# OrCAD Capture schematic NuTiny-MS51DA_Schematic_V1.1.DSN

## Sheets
1 Nu-Link-ME V3.0: size A4; title: Nu-Link-Me; rev: 3.0; note: 1
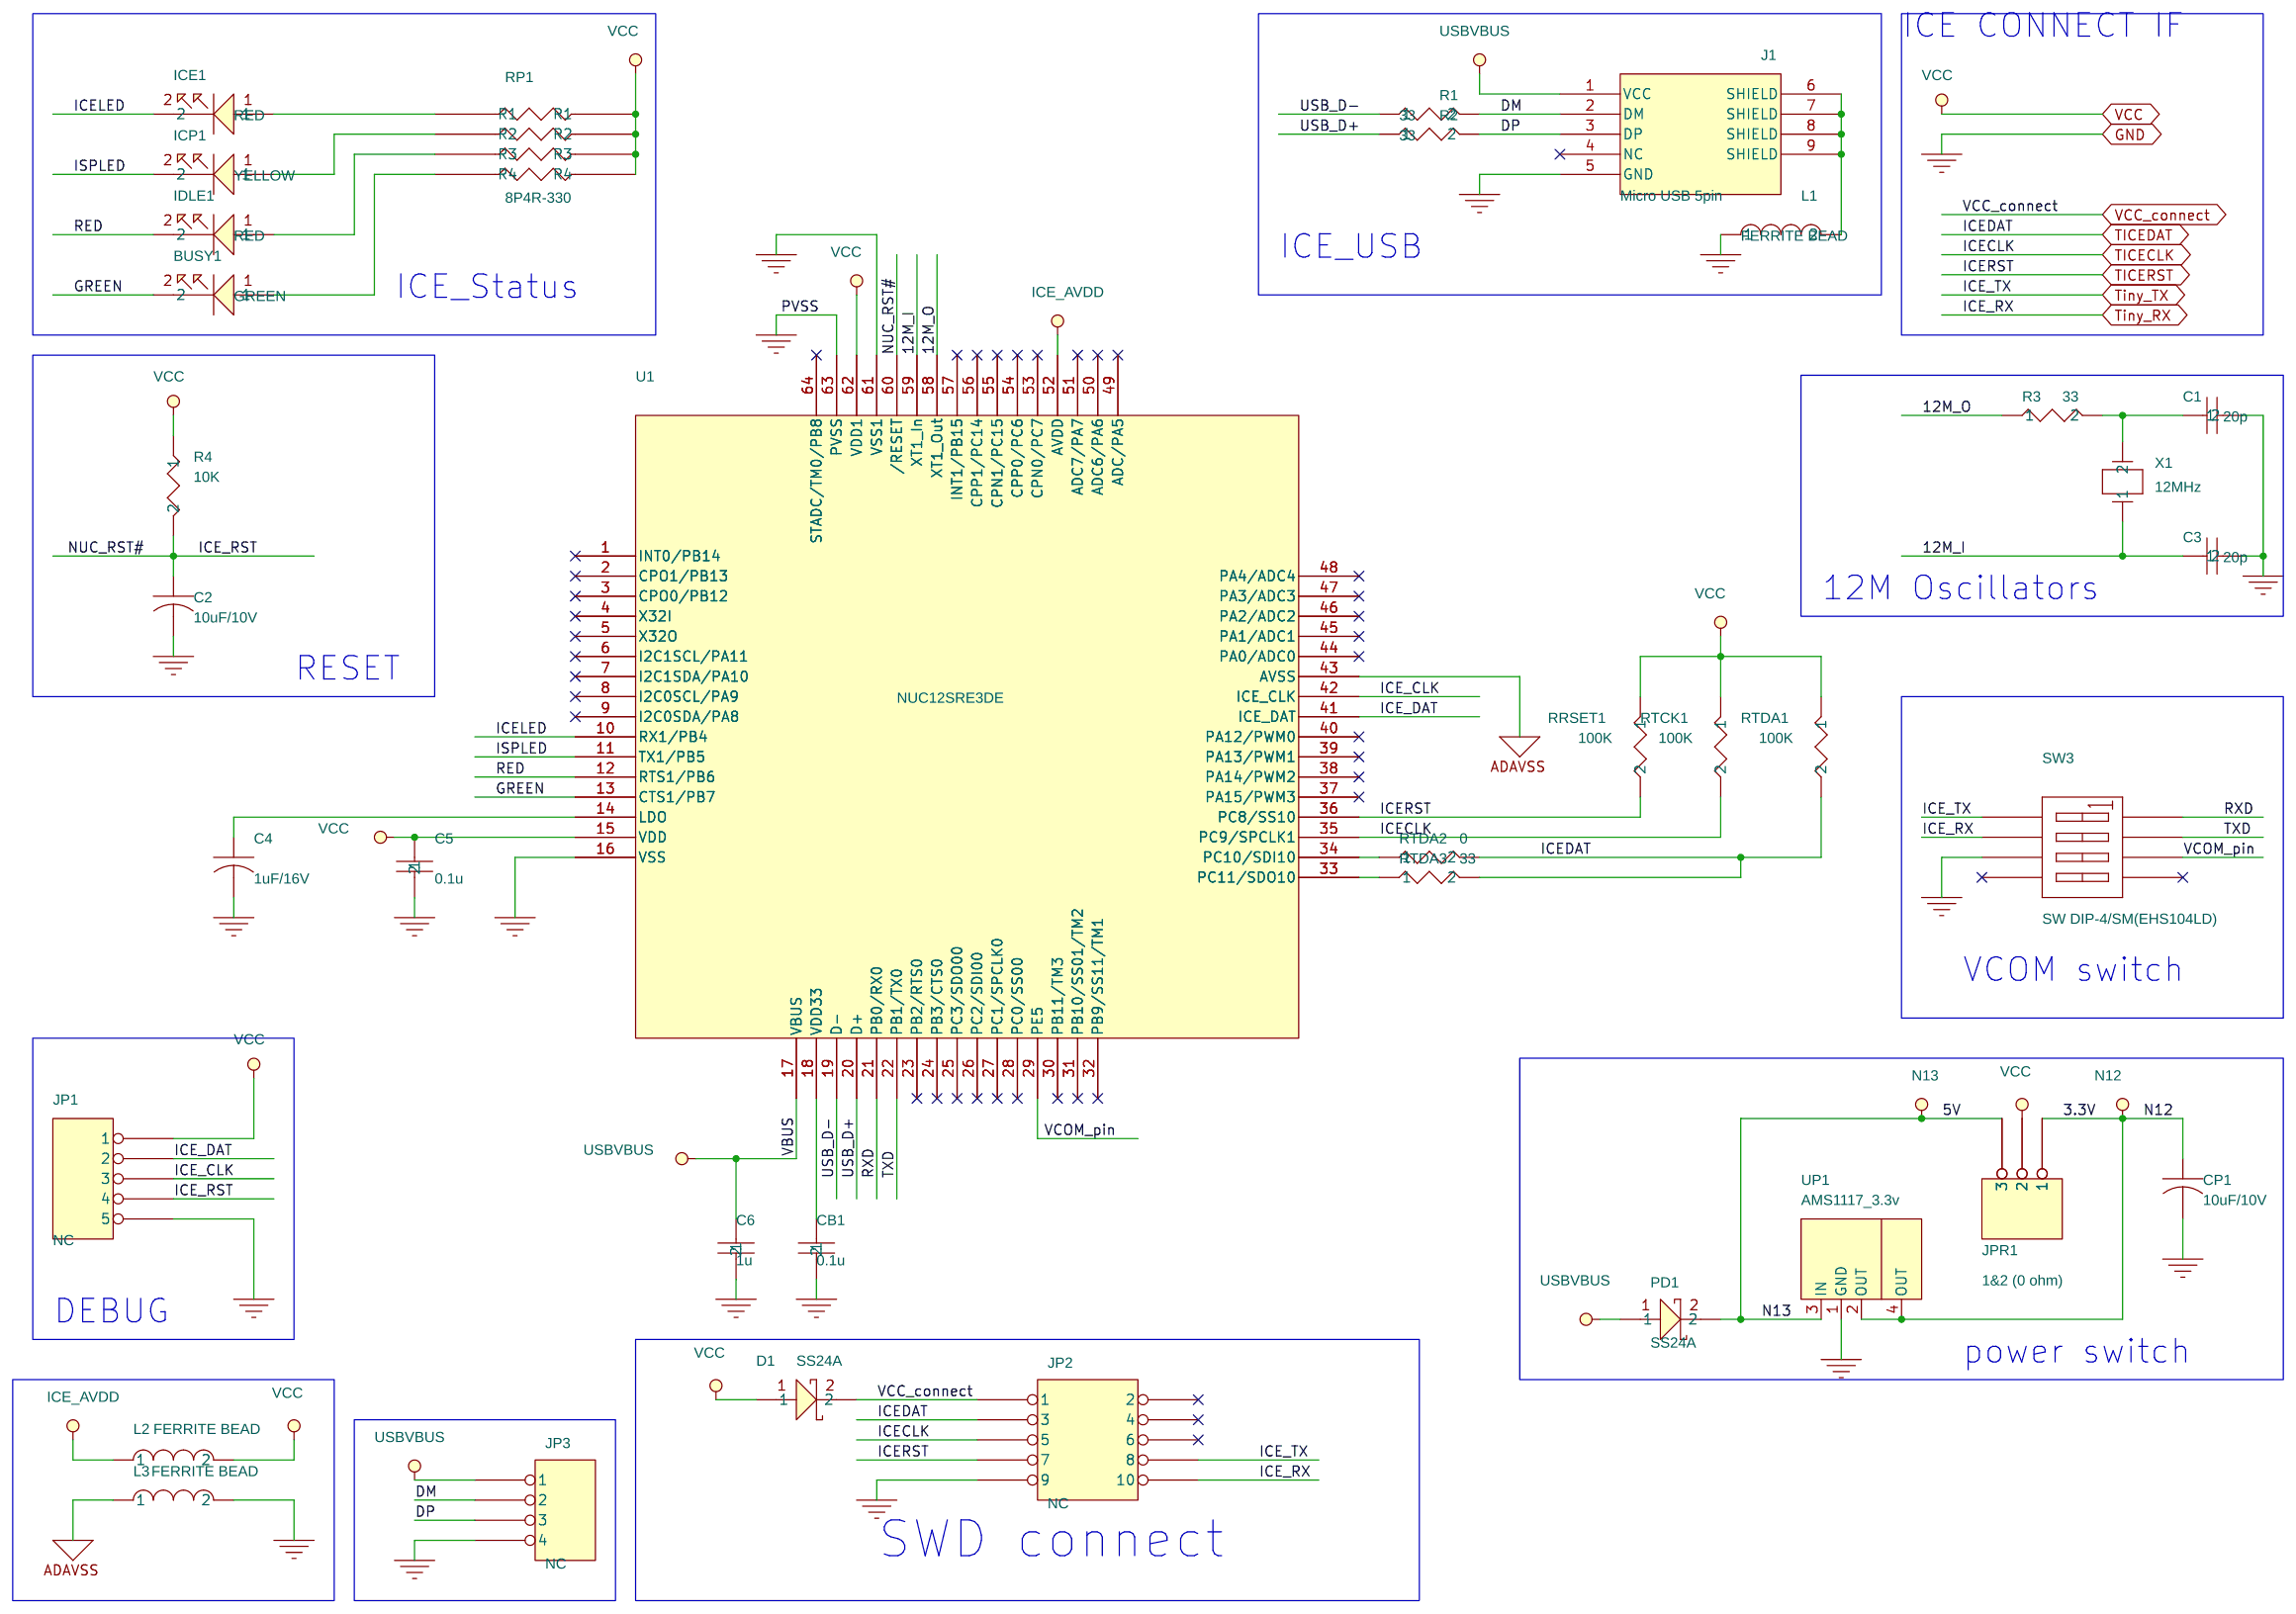
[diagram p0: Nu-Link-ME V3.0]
2 NuTiny-MS51DA: size A4; title: SDK Circuit; rev: 1.1; note: 2
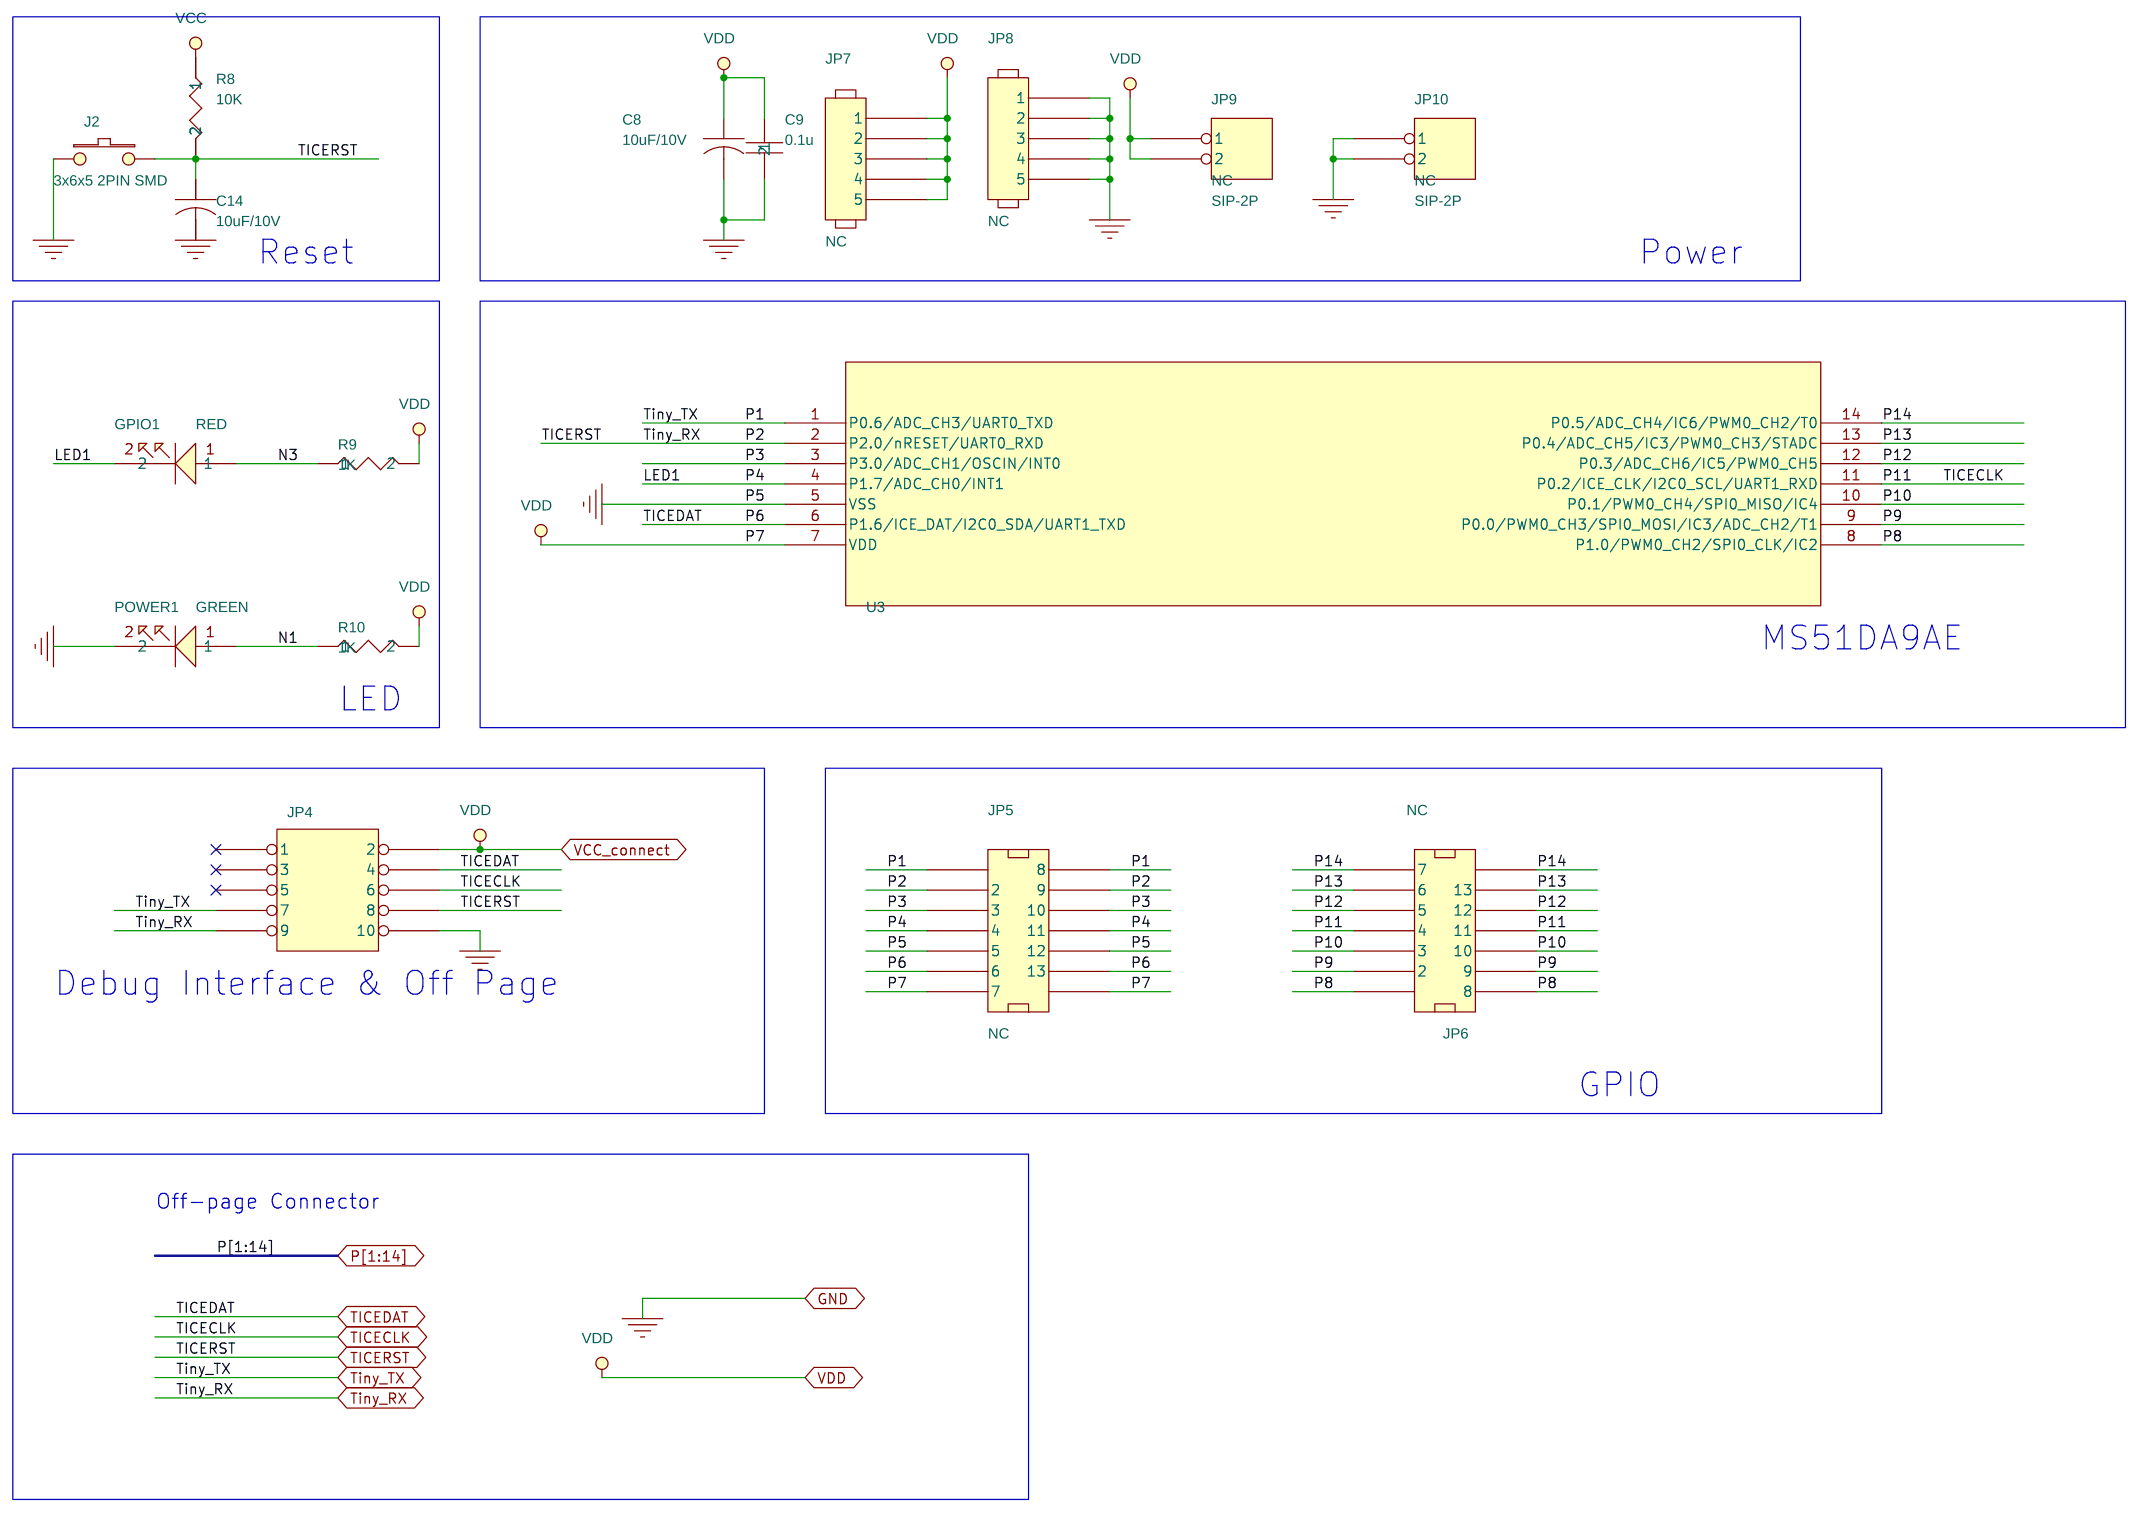
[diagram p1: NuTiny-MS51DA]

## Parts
sheet Nu-Link-ME V3.0
BUSY1  GREEN  [LED0805]
C1  20p  [C0603]
C2  10uF/10V  [TANT-A]
C3  20p  [C0603]
C4  1uF/16V  [TANT-A]
C5  0.1u  [C0603]
C6  1u  [C0603]
CB1  0.1u  [C0603]
CP1  10uF/10V  [TANT-A]
D1  SS24A  [RB060L]
ICE1  RED  [LED0805]
ICP1  YELLOW  [LED0805]
IDLE1  RED  [LED0805]
J1  Micro USB 5pin  [MICRO_USB_AB_LS]
JP1  NC  [HEADER05]
JP2  NC  [HEADER5X2]
JP3  NC  [HEADER04]
JPR1  1&2 (0 ohm)  [R0603X2]
L1  FERRITE BEAD  [L0603]
L2  FERRITE BEAD  [L0603]
L3  FERRITE BEAD  [L0603]
PD1  SS24A  [RB060L]
R1  33  [R0603]
R2  33  [R0603]
R3  33  [R0603]
R4  10K  [R0603]
RP1  8P4R-330  [8P4RA]
RRSET1  100K  [R0603]
RTCK1  100K  [R0603]
RTDA1  100K  [R0603]
RTDA2  0  [R0603]
RTDA3  33  [R0603]
SW3  SW DIP-4/SM(EHS104LD)  [SW1X4]
U1  NUC12SRE3DE  [NCU120_LQFP_64]
UP1  AMS1117_3.3v  [SOT-223-1]
X1  12MHz  [XTAL\LP\SMD]
sheet NuTiny-MS51DA
C8  10uF/10V  [TANT-A]
C9  0.1u  [C0603]
C14  10uF/10V  [TANT-A]
GPIO1  RED  [LED0805]
J2  3x6x5 2PIN SMD  [SW-2P-SMD]
JP4  NC  [HEADER5X2]
JP5  NC  [HEADER7X2]
JP6  NC  [HEADER7X2]
JP7  NC  [SIP-5P]
JP8  NC  [SIP-5P]
JP9  NC  [SIP-2P]
JP10  NC  [SIP-2P]
POWER1  GREEN  [LED0805]
R8  10K  [R0603]
R9  1K  [R0603]
R10  1K  [R0603]
U3  MS51DA9AE  [MCU_TSSOP_14]

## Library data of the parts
BUSY1 POWER1 = LED_GREEN: element: 0805 LED G (炊厚)
C1 = C_20p
C2 C8 C14 CP1 = C_10uF_10V
C3 = C_20p_1
C4 = C_1uF_16V
C5 C9 = C_0.1u
C6 = C_1u
CB1 = C_0.1u_1
D1 = D_SS24A_1
ICE1 = LED_RED_1
ICP1 = LED_YELLOW
GPIO1 IDLE1 = LED_RED
J1 = mini_USB_5pin
JP1 = HEADER_5_v2
JP2 JP4 = HEADER_5X2
JP3 = HEADER_4
JPR1 = HEADER_3: element: ¡]³s¨ì1pin VCC33)
L1 = FERRITE_BEAD_2
L2 = FERRITE_BEAD
L3 = FERRITE_BEAD_1
PD1 = D_SS24A
R1 = R_33
R2 = R_33_1
R3 = R_33_3
R4 R8 = R_10K
RP1 = 8P4R-330
RRSET1 = R_100K_2
RTCK1 = R_100K_1
RTDA1 = R_100K
RTDA2 = R_0
RTDA3 = R_33_2
SW3 = SW_DIP-4_SM
U1 = NCU120_LQFP_1
UP1 = TO-247_Regulator_10
X1 = Xtal_12MHz
J2 = PUSH_BOTTOM_(B): element: 3x6x5 2PIN SMDH(堵)
JP5 JP6 = CONN_SOCKET_7x2
JP7 = HEADER_5_1
JP8 = HEADER_5
JP9 = HEADER_2
JP10 = HEADER_2_1
R9 = R_1K
R10 = R_1K_1
U3 = MS51DA9AE

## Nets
3.3V: CP1.1 JPR1.1 UP1.2(OUT) UP1.4(OUT)
5V: JPR1.3 PD1.2 UP1.3(IN)
AVSS: L3.1 U1.43(AVSS)
GND: C1.2 C2.2 C3.2 C4.2 C5.2 C6.2 C8.2 C9.2 C14.2 CB1.2 CP1.2 J1.5(GND) J2.1 JP1.5 JP2.9 JP3.4 JP4.10 JP5.9(5) JP5.10(12) JP8.1 JP8.2 JP8.3 JP8.4 JP8.5 JP10.1 JP10.2 L1.1 L3.2 POWER1.2 SW3.3(A3) U1.16(VSS) U1.61(VSS1) U1.63(PVSS) U3.5(VSS) UP1.1(GND)
VCC: C5.1 D1.1 JP1.1 JPR1.2 L2.2 R4.1 RP1.2(R1) RP1.4(R2) RP1.6(R3) RP1.8(R4) RRSET1.1 RTCK1.1 RTDA1.1 U1.15(VDD) U1.62(VDD1)
12M_I: C3.1 U1.59(XT1_In) X1.1
12M_O: R3.1 U1.58(XT1_Out)
DM: J1.2(DM) JP3.2 R1.2
DP: J1.3(DP) JP3.3 R2.2
GREEN: BUSY1.2 U1.13(CTS1/PB7)
ICE_AVDD: L2.1 U1.52(AVDD)
ICE_CLK: JP1.3 U1.42(ICE_CLK)
ICE_DAT: JP1.2 U1.41(ICE_DAT)
ICE_RST: C2.1 JP1.4 R4.2 U1.60(/RESET)
ICELED: ICE1.2 U1.10(RX1/PB4)
ICERST: C14.1 J2.2 JP2.7 JP2.10 JP4.8 JP4.9 JP5.3(2) JP5.4(9) R8.2 RRSET1.2 SW3.2(A2) U1.36(PC8/SS10) U3.2(P2.0/nRESET/UART0_RXD)
ISPLED: ICP1.2 U1.11(TX1/PB5)
N1: POWER1.1 R10.1
N3: GPIO1.1 R9.1
P1: JP2.8 JP4.7 JP5.1 JP5.2(8) SW3.1(A1) U3.1(P0.6/ADC_CH3/UART0_TXD)
P3: JP5.5(3) JP5.6(10) U3.3(P3.0/ADC_CH1/OSCIN/INT0)
P4: GPIO1.2 JP5.7(4) JP5.8(11) U3.4(P1.7/ADC_CH0/INT1)
P6: JP2.3 JP4.4 JP5.11(6) JP5.12(13) RTDA1.2 RTDA2.2 RTDA3.2 U3.6(P1.6/ICE_DAT/I2C0_SDA/UART1_TXD)
P7: C8.1 C9.1 D1.2 JP2.1 JP4.2 JP5.13(7) JP5.14 JP7.1 JP7.2 JP7.3 JP7.4 JP7.5 JP9.1 JP9.2 R8.1 R9.2 R10.2 U3.7(VDD)
P8: JP6.1 JP6.2(8) U3.8(P1.0/PWM0_CH2/SPI0_CLK/IC2)
P9: JP6.3(2) JP6.4(9) U3.9(P0.0/PWM0_CH3/SPI0_MOSI/IC3/ADC_CH2/T1)
P10: JP6.5(3) JP6.6(10) U3.10(P0.1/PWM0_CH4/SPI0_MISO/IC4)
P11: JP2.5 JP4.6 JP6.7(4) JP6.8(11) RTCK1.2 U1.35(PC9/SPCLK1) U3.11(P0.2/ICE_CLK/I2C0_SCL/UART1_RXD)
P12: JP6.9(5) JP6.10(12) U3.12(P0.3/ADC_CH6/IC5/PWM0_CH5)
P13: JP6.11(6) JP6.12(13) U3.13(P0.4/ADC_CH5/IC3/PWM0_CH3/STADC)
P14: JP6.13(7) JP6.14 U3.14(P0.5/ADC_CH4/IC6/PWM0_CH2/T0)
RED: IDLE1.2 U1.12(RTS1/PB6)
RXD: SW3.8(B1) U1.21(PB0/RX0)
TXD: SW3.7(B2) U1.22(PB1/TX0)
USB_D+: R2.1 U1.20(D+)
USB_D-: R1.1 U1.19(D-)
USBVBUS: C6.1 J1.1(VCC) JP3.1 PD1.1 U1.17(VBUS)
VCOM_pin: SW3.6(B3) U1.29(PE5)
N00874: BUSY1.1 RP1.7(R4)
N00882: IDLE1.1 RP1.5(R3)
N00906: ICE1.1 RP1.1(R1)
N00938: ICP1.1 RP1.3(R2)
N07793: C1.1 R3.2 X1.2
N16812063: C4.1 U1.14(LDO)
N16812255: CB1.1 U1.18(VDD33)
N16812376: RTDA3.1 U1.33(PC11/SDO10)
N17861502: RTDA2.1 U1.34(PC10/SDI10)
N18771284: J1.6(SHIELD) J1.7(SHIELD) J1.8(SHIELD) J1.9(SHIELD) L1.2

Not connected (* = marked no-connect by the designer): J1 4(NC)*; JP2 2* 4* 6*; JP4 1* 3* 5*; SW3 4(A4)* 5(B4)*; U1 1(INT0/PB14)* 2(CPO1/PB13)* 3(CPO0/PB12)* 4(X32I)* 5(X32O)* 6(I2C1SCL/PA11)* 7(I2C1SDA/PA10)* 8(I2C0SCL/PA9)* 9(I2C0SDA/PA8)* 23(PB2/RTS0)* 24(PB3/CTS0)* 25(PC3/SDO00)* 26(PC2/SDI00)* 27(PC1/SPCLK0)* 28(PC0/SS00)* 30(PB11/TM3)* 31(PB10/SS01/TM2)* 32(PB9/SS11/TM1)* 37(PA15/PWM3)* 38(PA14/PWM2)* 39(PA13/PWM1)* 40(PA12/PWM0)* 44(PA0/ADC0)* 45(PA1/ADC1)* 46(PA2/ADC2)* 47(PA3/ADC3)* 48(PA4/ADC4)* 49(ADC/PA5)* 50(ADC6/PA6)* 51(ADC7/PA7)* 53(CPN0/PC7)* 54(CPP0/PC6)* 55(CPN1/PC15)* 56(CPP1/PC14)* 57(INT1/PB15)* 64(STADC/TM0/PB8)*

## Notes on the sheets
sheet 1
- ICE CONNECT IF
- ICE_USB
- ICE_Status
- 12M Oscillators
- RESET
- VCOM switch
- DEBUG
- power switch
- SWD connect
sheet 2
- Reset
- Power
- MS51DA9AE
- LED
- Debug Interface & Off Page
- GPIO
- Off-page Connector
